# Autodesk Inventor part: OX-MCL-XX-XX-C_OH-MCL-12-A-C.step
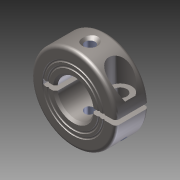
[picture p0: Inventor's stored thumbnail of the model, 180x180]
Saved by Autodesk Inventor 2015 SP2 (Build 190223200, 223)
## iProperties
Created: 2018-02
Part Number: OX-MCL-XX-XX-C_OH-MCL-12-A-C.step
Material: Generic
Document SubType Name: Modeling
Designer: 3dxAdmin
Density: 1 g/cm^3
Appearance: Default
Author: 3dxAdmin
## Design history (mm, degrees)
feature "Base1"
node "OX-MCL-XX-XX-C_OH-MCL-12-A-C.step"
